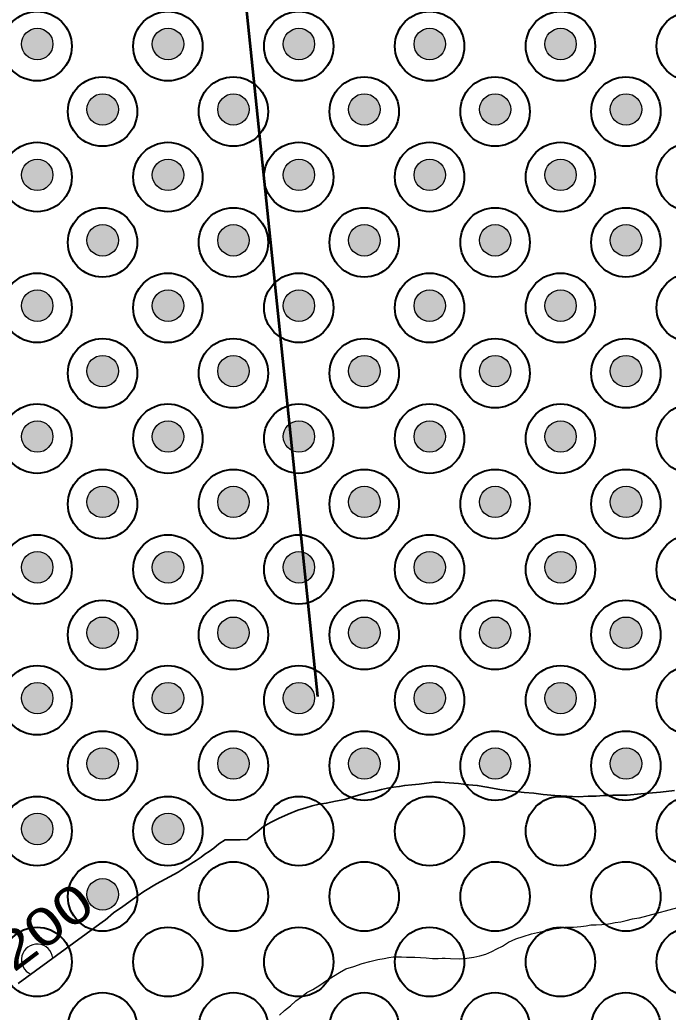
# Model space of a CAD drawing. Extents: x -10.5 to 30.8, y 18.4 to 58.7.
# Drawn here: x -2.95 to 0.55, y 23.88 to 29.24 of the extents above; entities that cross this region are included whole.
import ezdxf

# ---------------------------------------------------------------- set-up
doc = ezdxf.new("R2010")
doc.units = 0
doc.header["$LTSCALE"] = 0.08
for name, color, linetype, lineweight in [('10', 7, 'Continuous', 35), ('22', 7, 'Continuous', 25), ('40', 7, 'Continuous', 53), ('44', 7, 'Continuous', 35), ('6', 7, 'Continuous', 40), ('8', 7, 'Continuous', 25)]:
    doc.layers.add(name, color=color, linetype=linetype, lineweight=lineweight)

msp = doc.modelspace()

# ---------------------------------------------------------------- hatches: boundary and pattern name
at = {"layer": '22'}
for points in [[(-2.80062, 29.16988, 1), (-2.92083, 29.04967, 1)], [(-2.09351, 29.16988, 1), (-2.21372, 29.04967, 1)], [(-1.38641, 29.16988, 1), (-1.50661, 29.04967, 1)], [(-0.6793, 29.16988, 1), (-0.79951, 29.04967, 1)], [(0.02781, 29.16988, 1), (-0.0924, 29.04967, 1)], [(-2.44707, 28.81632, 1), (-2.56727, 28.69611, 1)], [(-1.73996, 28.81632, 1), (-1.86017, 28.69611, 1)], [(-1.03285, 28.81632, 1), (-1.15306, 28.69611, 1)], [(-0.32575, 28.81632, 1), (-0.44595, 28.69611, 1)], [(0.38136, 28.81632, 1), (0.26115, 28.69611, 1)], [(-2.80062, 28.46277, 1), (-2.92083, 28.34256, 1)], [(-2.09351, 28.46277, 1), (-2.21372, 28.34256, 1)], [(-1.38641, 28.46277, 1), (-1.50661, 28.34256, 1)], [(-0.6793, 28.46277, 1), (-0.79951, 28.34256, 1)], [(0.02781, 28.46277, 1), (-0.0924, 28.34256, 1)], [(-2.44707, 28.10922, 1), (-2.56727, 27.98901, 1)], [(-1.73996, 28.10922, 1), (-1.86017, 27.98901, 1)], [(-1.03285, 28.10922, 1), (-1.15306, 27.98901, 1)], [(-0.32575, 28.10922, 1), (-0.44595, 27.98901, 1)], [(0.38136, 28.10922, 1), (0.26115, 27.98901, 1)], [(-2.80062, 27.75566, 1), (-2.92083, 27.63545, 1)], [(-2.09351, 27.75566, 1), (-2.21372, 27.63545, 1)], [(-1.38641, 27.75566, 1), (-1.50661, 27.63545, 1)], [(-0.6793, 27.75566, 1), (-0.79951, 27.63545, 1)], [(0.02781, 27.75566, 1), (-0.0924, 27.63545, 1)], [(-2.44707, 27.40211, 1), (-2.56727, 27.2819, 1)], [(-1.73996, 27.40211, 1), (-1.86017, 27.2819, 1)], [(-1.03285, 27.40211, 1), (-1.15306, 27.2819, 1)], [(-0.32575, 27.40211, 1), (-0.44595, 27.2819, 1)], [(0.38136, 27.40211, 1), (0.26115, 27.2819, 1)], [(-2.80062, 27.04856, 1), (-2.92083, 26.92835, 1)], [(-2.09351, 27.04856, 1), (-2.21372, 26.92835, 1)], [(-1.38641, 27.04856, 1), (-1.50661, 26.92835, 1)], [(-0.6793, 27.04856, 1), (-0.79951, 26.92835, 1)], [(0.02781, 27.04856, 1), (-0.0924, 26.92835, 1)], [(-2.44707, 26.695, 1), (-2.56727, 26.57479, 1)], [(-1.73996, 26.695, 1), (-1.86017, 26.57479, 1)], [(-1.03285, 26.695, 1), (-1.15306, 26.57479, 1)], [(-0.32575, 26.695, 1), (-0.44595, 26.57479, 1)], [(0.38136, 26.695, 1), (0.26115, 26.57479, 1)], [(-2.80062, 26.34145, 1), (-2.92083, 26.22124, 1)], [(-2.09351, 26.34145, 1), (-2.21372, 26.22124, 1)], [(-1.38641, 26.34145, 1), (-1.50661, 26.22124, 1)], [(-0.6793, 26.34145, 1), (-0.79951, 26.22124, 1)], [(0.02781, 26.34145, 1), (-0.0924, 26.22124, 1)], [(-2.44707, 25.98789, 1), (-2.56727, 25.86769, 1)], [(-1.73996, 25.98789, 1), (-1.86017, 25.86769, 1)], [(-1.03285, 25.98789, 1), (-1.15306, 25.86769, 1)], [(-0.32575, 25.98789, 1), (-0.44595, 25.86769, 1)], [(0.38136, 25.98789, 1), (0.26115, 25.86769, 1)], [(-2.80062, 25.63434, 1), (-2.92083, 25.51413, 1)], [(-2.09351, 25.63434, 1), (-2.21372, 25.51413, 1)], [(-1.38641, 25.63434, 1), (-1.50661, 25.51413, 1)], [(-0.6793, 25.63434, 1), (-0.79951, 25.51413, 1)], [(0.02781, 25.63434, 1), (-0.0924, 25.51413, 1)], [(-2.44707, 25.28079, 1), (-2.56727, 25.16058, 1)], [(-1.73996, 25.28079, 1), (-1.86017, 25.16058, 1)], [(-1.03285, 25.28079, 1), (-1.15306, 25.16058, 1)], [(-0.32575, 25.28079, 1), (-0.44595, 25.16058, 1)], [(0.38136, 25.28079, 1), (0.26115, 25.16058, 1)], [(-2.80062, 24.92723, 1), (-2.92083, 24.80703, 1)], [(-2.09351, 24.92723, 1), (-2.21372, 24.80703, 1)], [(-2.44707, 24.57368, 1), (-2.56727, 24.45347, 1)]]:
    msp.add_hatch(color=256, dxfattribs=at).paths.add_polyline_path(points)

# ---------------------------------------------------------------- linework, layer by layer
at = {"layer": '10'}
msp.add_line((-2.96336, 24.03259), (-2.5019, 24.36806), dxfattribs=at)
for points in [[(-1.72684, 24.81045), (-1.71712, 24.81801), (-1.67258, 24.8514), (-1.63798, 24.8796), (-1.60077, 24.90284), (-1.556, 24.92373), (-1.50375, 24.94727), (-1.45145, 24.9683), (-1.40905, 24.98164), (-1.37413, 24.99232), (-1.33665, 25.00056), (-1.29912, 25.0063), (-1.24915, 25.01728), (-1.19914, 25.02576), (-1.14925, 25.04174), (-1.10434, 25.05513), (-1.06691, 25.06586), (-1.0319, 25.07155), (-0.99944, 25.07969), (-0.96697, 25.08783), (-0.93446, 25.09347), (-0.90442, 25.09655), (-0.87442, 25.10214), (-0.83685, 25.10538), (-0.79676, 25.10866), (-0.75675, 25.11444), (-0.7142, 25.12028), (-0.6816, 25.12091), (-0.63386, 25.11684), (-0.58361, 25.11282), (-0.53082, 25.10634), (-0.48308, 25.10227), (-0.43023, 25.09329), (-0.35974, 25.07966), (-0.29435, 25.07092), (-0.22903, 25.06469), (-0.17626, 25.06072), (-0.12598, 25.05419), (-0.06315, 25.04791), (0.00215, 25.04418), (0.06493, 25.0404), (0.11755, 25.04393), (0.16017, 25.04476), (0.20025, 25.04805), (0.23035, 25.04863), (0.25041, 25.04902), (0.32814, 25.05054), (0.40078, 25.05696), (0.50848, 25.06657), (0.58357, 25.07554)], [(-2.5019, 24.36806), (-2.49316, 24.37497), (-2.44835, 24.41293), (-2.3985, 24.44845), (-2.34614, 24.48649), (-2.28382, 24.52963), (-2.21645, 24.57032), (-2.09912, 24.63403), (-2.04424, 24.66959), (-2.00185, 24.69753), (-1.97442, 24.71531), (-1.95448, 24.73052), (-1.93204, 24.74575), (-1.90711, 24.76351), (-1.87971, 24.78629), (-1.8448, 24.80915), (-1.81494, 24.80767), (-1.76425, 24.80831), (-1.72684, 24.81045)]]:
    msp.add_lwpolyline(points, dxfattribs=at)
at = {"layer": '22', "lineweight": 35}
msp.add_line((-2.96336, 24.03259), (-2.5019, 24.36806), dxfattribs=at)
at = {"layer": '22'}
msp.add_line((-2.89504, 24.08226), (-2.77617, 24.16868), dxfattribs=at)
at = {"layer": '22', "lineweight": 35}
for points in [[(-1.72684, 24.81045), (-1.71712, 24.81801), (-1.67258, 24.8514), (-1.63798, 24.8796), (-1.60077, 24.90284), (-1.556, 24.92373), (-1.50375, 24.94727), (-1.45145, 24.9683), (-1.40905, 24.98164), (-1.37413, 24.99232), (-1.33665, 25.00056), (-1.29912, 25.0063), (-1.24915, 25.01728), (-1.19914, 25.02576), (-1.14925, 25.04174), (-1.10434, 25.05513), (-1.06691, 25.06586), (-1.0319, 25.07155), (-0.99944, 25.07969), (-0.96697, 25.08783), (-0.93446, 25.09347), (-0.90442, 25.09655), (-0.87442, 25.10214), (-0.83685, 25.10538), (-0.79676, 25.10866), (-0.75675, 25.11444), (-0.7142, 25.12028), (-0.6816, 25.12091), (-0.63386, 25.11684), (-0.58361, 25.11282), (-0.53082, 25.10634), (-0.48308, 25.10227), (-0.43023, 25.09329), (-0.35974, 25.07966), (-0.29435, 25.07092), (-0.22903, 25.06469), (-0.17626, 25.06072), (-0.12598, 25.05419), (-0.06315, 25.04791), (0.00215, 25.04418), (0.06493, 25.0404), (0.11755, 25.04393), (0.16017, 25.04476), (0.20025, 25.04805), (0.23035, 25.04863), (0.25041, 25.04902), (0.32814, 25.05054), (0.40078, 25.05696), (0.50848, 25.06657), (0.58357, 25.07554)], [(-2.5019, 24.36806), (-2.49316, 24.37497), (-2.44835, 24.41293), (-2.3985, 24.44845), (-2.34614, 24.48649), (-2.28382, 24.52963), (-2.21645, 24.57032), (-2.09912, 24.63403), (-2.04424, 24.66959), (-2.00185, 24.69753), (-1.97442, 24.71531), (-1.95448, 24.73052), (-1.93204, 24.74575), (-1.90711, 24.76351), (-1.87971, 24.78629), (-1.8448, 24.80915), (-1.81494, 24.80767), (-1.76425, 24.80831), (-1.72684, 24.81045)]]:
    msp.add_lwpolyline(points, dxfattribs=at)
at = {"layer": '22'}
for centre in [(-2.86072, 29.10977), (-2.15362, 29.10977), (-1.44651, 29.10977), (-0.7394, 29.10977), (-0.0323, 29.10977), (-2.50717, 28.75622), (-1.80006, 28.75622), (-1.09296, 28.75622), (-0.38585, 28.75622), (0.32126, 28.75622), (-2.86072, 28.40266), (-2.15362, 28.40266), (-1.44651, 28.40266), (-0.7394, 28.40266), (-0.0323, 28.40266), (-2.50717, 28.04911), (-1.80006, 28.04911), (-1.09296, 28.04911), (-0.38585, 28.04911), (0.32126, 28.04911), (-2.86072, 27.69556), (-2.15362, 27.69556), (-1.44651, 27.69556), (-0.7394, 27.69556), (-0.0323, 27.69556), (-2.50717, 27.342), (-1.80006, 27.342), (-1.09296, 27.342), (-0.38585, 27.342), (0.32126, 27.342), (-2.86072, 26.98845), (-2.15362, 26.98845), (-1.44651, 26.98845), (-0.7394, 26.98845), (-0.0323, 26.98845), (-2.50717, 26.6349), (-1.80006, 26.6349), (-1.09296, 26.6349), (-0.38585, 26.6349), (0.32126, 26.6349), (-2.86072, 26.28134), (-2.15362, 26.28134), (-1.44651, 26.28134), (-0.7394, 26.28134), (-0.0323, 26.28134), (-2.50717, 25.92779), (-1.80006, 25.92779), (-1.09296, 25.92779), (-0.38585, 25.92779), (0.32126, 25.92779), (-2.86072, 25.57424), (-2.15362, 25.57424), (-1.44651, 25.57424), (-0.7394, 25.57424), (-0.0323, 25.57424), (-2.50717, 25.22068), (-1.80006, 25.22068), (-1.09296, 25.22068), (-0.38585, 25.22068), (0.32126, 25.22068), (-2.86072, 24.86713), (-2.15362, 24.86713), (-2.50717, 24.51358)]:
    msp.add_circle(centre, 0.085, dxfattribs=at)
msp.add_arc((-2.86072, 24.16002), 0.085, 5.84163, 246.19089, dxfattribs=at)
msp.add_arc((-2.86072, 24.16002), 0.085, 5.84163, 246.19089, dxfattribs=at)
at = {"layer": '40'}
msp.add_line((-2.18418, 33.68745), (-1.34625, 25.58227), dxfattribs=at)
at = {"layer": '44'}
for points in [[(0.58357, 25.07554), (0.50848, 25.06657), (0.40078, 25.05696), (0.32814, 25.05054), (0.25041, 25.04902), (0.23035, 25.04863), (0.20025, 25.04805), (0.16017, 25.04476), (0.11755, 25.04393), (0.06493, 25.0404), (0.00215, 25.04418), (-0.06315, 25.04791), (-0.12598, 25.05419), (-0.17626, 25.06072), (-0.22903, 25.06469), (-0.29435, 25.07092), (-0.35974, 25.07966), (-0.43023, 25.09329), (-0.48308, 25.10227), (-0.53082, 25.10634), (-0.58361, 25.11282), (-0.63386, 25.11684), (-0.6816, 25.12091), (-0.7142, 25.12028), (-0.75675, 25.11444), (-0.79676, 25.10866), (-0.83685, 25.10538), (-0.87442, 25.10214), (-0.90442, 25.09655), (-0.93446, 25.09347), (-0.96697, 25.08783), (-0.99944, 25.07969), (-1.0319, 25.07155), (-1.06691, 25.06586), (-1.10434, 25.05513), (-1.14925, 25.04174), (-1.19914, 25.02576), (-1.24915, 25.01728), (-1.29912, 25.0063), (-1.33665, 25.00056), (-1.37413, 24.99232), (-1.40905, 24.98164), (-1.45145, 24.9683), (-1.50375, 24.94727), (-1.556, 24.92373), (-1.60077, 24.90284), (-1.63798, 24.8796), (-1.67258, 24.8514), (-1.71712, 24.81801), (-1.72684, 24.81045)], [(-1.72684, 24.81045), (-1.76425, 24.80831), (-1.81494, 24.80767), (-1.8448, 24.80915), (-1.87971, 24.78629), (-1.90711, 24.76351), (-1.93204, 24.74575), (-1.95448, 24.73052), (-1.97442, 24.71531), (-2.00185, 24.69753), (-2.04424, 24.66959), (-2.09912, 24.63403), (-2.21645, 24.57032), (-2.28382, 24.52963), (-2.34614, 24.48649), (-2.3985, 24.44845), (-2.44835, 24.41293), (-2.49316, 24.37497), (-2.5019, 24.36806), (-2.96336, 24.03259)]]:
    msp.add_lwpolyline(points, dxfattribs=at)
at = {"layer": '6'}
for centre in [(-2.8613, 29.09823), (-2.1542, 29.09823), (-1.44709, 29.09823), (-0.73998, 29.09823), (-0.03287, 29.09823), (0.67423, 29.09823), (-2.50775, 28.74468), (-1.80064, 28.74468), (-1.09353, 28.74468), (-0.38643, 28.74468), (0.32068, 28.74468), (-2.8613, 28.39112), (-2.1542, 28.39112), (-1.44709, 28.39112), (-0.73998, 28.39112), (-0.03287, 28.39112), (0.67423, 28.39112), (-2.50775, 28.03757), (-1.80064, 28.03757), (-1.09353, 28.03757), (-0.38643, 28.03757), (0.32068, 28.03757), (-2.8613, 27.68402), (-2.1542, 27.68402), (-1.44709, 27.68402), (-0.73998, 27.68402), (-0.03287, 27.68402), (0.67423, 27.68402), (-2.50775, 27.33046), (-1.80064, 27.33046), (-1.09353, 27.33046), (-0.38643, 27.33046), (0.32068, 27.33046), (-2.8613, 26.97691), (-2.1542, 26.97691), (-1.44709, 26.97691), (-0.73998, 26.97691), (-0.03287, 26.97691), (0.67423, 26.97691), (-2.50775, 26.62336), (-1.80064, 26.62336), (-1.09353, 26.62336), (-0.38643, 26.62336), (0.32068, 26.62336), (-2.8613, 26.2698), (-2.1542, 26.2698), (-1.44709, 26.2698), (-0.73998, 26.2698), (-0.03287, 26.2698), (0.67423, 26.2698), (-2.50775, 25.91625), (-1.80064, 25.91625), (-1.09353, 25.91625), (-0.38643, 25.91625), (0.32068, 25.91625), (-2.8613, 25.5627), (-2.1542, 25.5627), (-1.44709, 25.5627), (-0.73998, 25.5627), (-0.03287, 25.5627), (0.67423, 25.5627), (-2.50775, 25.20914), (-1.80064, 25.20914), (-1.09353, 25.20914), (-0.38643, 25.20914), (0.32068, 25.20914), (-2.8613, 24.85559), (-2.1542, 24.85559), (-1.44709, 24.85559), (-0.73998, 24.85559), (-0.03287, 24.85559), (0.67423, 24.85559), (-2.50775, 24.50204), (-1.80064, 24.50204), (-1.09353, 24.50204), (-0.38643, 24.50204), (0.32068, 24.50204), (-2.8613, 24.14848), (-2.1542, 24.14848), (-1.44709, 24.14848), (-0.73998, 24.14848), (-0.03287, 24.14848), (0.67423, 24.14848), (-2.50775, 23.79493), (-1.80064, 23.79493), (-1.09353, 23.79493), (-0.38643, 23.79493), (0.32068, 23.79493)]:
    msp.add_circle(centre, 0.1875, dxfattribs=at)
at = {"layer": '8'}
for points in [[(-1.72684, 24.81045), (-1.71712, 24.81801), (-1.67258, 24.8514), (-1.63798, 24.8796), (-1.60077, 24.90284), (-1.556, 24.92373), (-1.50375, 24.94727), (-1.45145, 24.9683), (-1.40905, 24.98164), (-1.37413, 24.99232), (-1.33665, 25.00056), (-1.29912, 25.0063), (-1.24915, 25.01728), (-1.19914, 25.02576), (-1.14925, 25.04174), (-1.10434, 25.05513), (-1.06691, 25.06586), (-1.0319, 25.07155), (-0.99944, 25.07969), (-0.96697, 25.08783), (-0.93446, 25.09347), (-0.90442, 25.09655), (-0.87442, 25.10214), (-0.83685, 25.10538), (-0.79676, 25.10866), (-0.75675, 25.11444), (-0.7142, 25.12028), (-0.6816, 25.12091), (-0.63386, 25.11684), (-0.58361, 25.11282), (-0.53082, 25.10634), (-0.48308, 25.10227), (-0.43023, 25.09329), (-0.35974, 25.07966), (-0.29435, 25.07092), (-0.22903, 25.06469), (-0.17626, 25.06072), (-0.12598, 25.05419), (-0.06315, 25.04791), (0.00215, 25.04418), (0.06493, 25.0404), (0.11755, 25.04393), (0.16017, 25.04476), (0.20025, 25.04805), (0.23035, 25.04863), (0.25041, 25.04902), (0.32814, 25.05054), (0.40078, 25.05696), (0.50848, 25.06657), (0.58357, 25.07554)], [(-2.5019, 24.36806), (-2.49316, 24.37497), (-2.44835, 24.41293), (-2.3985, 24.44845), (-2.34614, 24.48649), (-2.28382, 24.52963), (-2.21645, 24.57032), (-2.09912, 24.63403), (-2.04424, 24.66959), (-2.00185, 24.69753), (-1.97442, 24.71531), (-1.95448, 24.73052), (-1.93204, 24.74575), (-1.90711, 24.76351), (-1.87971, 24.78629), (-1.8448, 24.80915), (-1.81494, 24.80767), (-1.76425, 24.80831), (-1.72684, 24.81045)], [(-1.55158, 23.86054), (-1.52445, 23.88609), (-1.49231, 23.91173), (-1.46268, 23.93733), (-1.433, 23.96042), (-1.40332, 23.98352), (-1.371, 23.99916), (-1.33379, 24.0224), (-1.29663, 24.04814), (-1.25943, 24.07139), (-1.2272, 24.09203), (-1.1924, 24.11022), (-1.15, 24.12356), (-1.10514, 24.13944), (-1.06269, 24.15028), (-1.02025, 24.16111), (-0.98523, 24.1668), (-0.96025, 24.17229), (-0.93772, 24.17523), (-0.91766, 24.17562), (-0.89258, 24.17611), (-0.86495, 24.17415), (-0.84489, 24.17454), (-0.81981, 24.17503), (-0.78967, 24.17311), (-0.75954, 24.1712), (-0.72434, 24.16688), (-0.69424, 24.16747), (-0.67168, 24.16791), (-0.65663, 24.1682), (-0.62649, 24.16629), (-0.5788, 24.16472), (-0.53872, 24.168), (-0.5012, 24.17374), (-0.46873, 24.18188), (-0.43626, 24.19001), (-0.40394, 24.20566), (-0.37659, 24.2187), (-0.34677, 24.23429), (-0.31453, 24.25493), (-0.27473, 24.27322), (-0.23484, 24.28651), (-0.18993, 24.29989), (-0.13996, 24.31088), (-0.10248, 24.31911), (-0.07001, 24.32725), (-0.03997, 24.33034), (-0.00746, 24.33598), (0.03768, 24.33686), (0.07776, 24.34014), (0.10529, 24.34318), (0.13028, 24.34867), (0.16037, 24.34926), (0.19047, 24.34985), (0.2155, 24.35284), (0.23802, 24.35578), (0.26301, 24.36127), (0.29305, 24.36436), (0.32301, 24.37244), (0.35547, 24.38058), (0.39048, 24.38627), (0.39418, 24.3869), (0.90241, 24.52326)]]:
    msp.add_lwpolyline(points, dxfattribs=at)

# ---------------------------------------------------------------- texts
at = {"layer": '8', "width": 1.25}
msp.add_text('200', height=0.2032, rotation=37, dxfattribs=at).set_placement((-2.98734, 24.08806))

doc.saveas('drawing.dxf')
